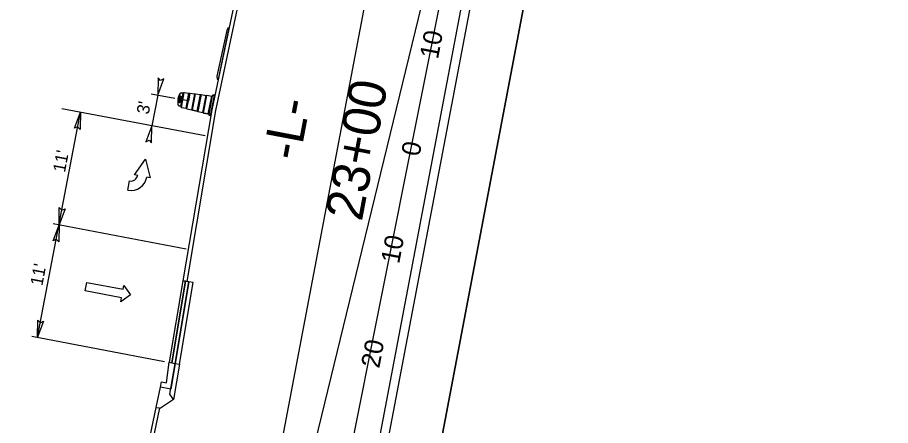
# Model space of a CAD drawing. Extents: x 1615680 to 1617075, y 898420 to 901168.
# Drawn here: x 1616656.3 to 1617075.3, y 899834.6 to 900030.6 of the extents above; entities that cross this region are included whole.
import ezdxf

# ---------------------------------------------------------------- set-up
doc = ezdxf.new("R2010")
doc.units = 0
for name, color, linetype in [('Default', 7, 'Continuous'), ('DEV BORDER CELL', 7, 'Continuous'), ('DEV DRUM SECTIONAL VIEW CELL', 7, 'Continuous'), ('Gray Area Fill Shapes', 7, 'Continuous'), ('North Arrow', 7, 'Continuous'), ('Old_Level_11', 7, 'Continuous'), ('Prop CMT Pvmt Course 1', 7, 'Continuous'), ('Prop CMT Pvmt Course 2', 7, 'Continuous'), ('Prop CMT Pvmt Course 3', 7, 'Continuous'), ('Prop CMT Subgrade Earthwork', 7, 'Continuous'), ('Prop Conc 4in Sidewalk', 7, 'Continuous'), ('Prop Conc Curb and Gutter', 7, 'Continuous'), ('Prop Conc Island Cover', 7, 'Continuous'), ('Prop Dimension Text', 7, 'Continuous'), ('Prop XS Finish Grade', 7, 'Continuous'), ('Prop XS Offset Labels', 7, 'Continuous'), ('Prop XS Station Labels', 7, 'Continuous'), ('Scratch_Level_0', 7, 'Continuous'), ('Scratch_Level_9', 7, 'Continuous'), ('Sheet Clip Boundary CELL', 7, 'Continuous'), ('Sheet Cross Section CELL', 7, 'Continuous'), ('Sheet Plot Border Outside CELL', 7, 'Continuous')]:
    doc.layers.add(name, color=color, linetype=linetype)

msp = doc.modelspace()

# ---------------------------------------------------------------- linework, layer by layer
at = {"layer": 'Default'}
for points in [[(1616723.79, 900001.53), (1616723.65, 899993.31), (1616726.58, 900001.05), (1616724.97, 900000.3)], [(1616683.66, 899977.39), (1616686.54, 899985.09), (1616686.44, 899976.82), (1616685.22, 899978.1)], [(1616720.71, 899970.36), (1616720.85, 899978.58), (1616717.91, 899970.84), (1616719.52, 899971.59)], [(1616679.16, 899938.75), (1616676.28, 899931.05), (1616676.39, 899939.33), (1616677.61, 899938.04)], [(1616673.4, 899923.36), (1616676.28, 899931.05), (1616676.18, 899922.78), (1616674.96, 899924.07)], [(1616668.91, 899884.72), (1616666.02, 899877.02), (1616666.13, 899885.29), (1616667.35, 899884.01)]]:
    msp.add_lwpolyline(points, close=True, dxfattribs=at)
at = {"layer": 'DEV BORDER CELL'}
msp.add_lwpolyline([(1616014.55, 901139.21), (1615734.74, 899665.53), (1616766.32, 899469.67), (1617046.12, 900943.35)], close=True, dxfattribs=at)
at = {"layer": 'DEV DRUM SECTIONAL VIEW CELL'}
for p, q in [((1616734.63, 899992.82), (1616734.6, 899992.83)), ((1616734.7, 899988.02), (1616735.87, 899994.18)), ((1616734.99, 899987.43), (1616736.36, 899994.63)), ((1616735.87, 899994.18), (1616735.15, 899994.32)), ((1616736.36, 899994.63), (1616738.66, 899994.19)), ((1616737.3, 899986.99), (1616738.66, 899994.19)), ((1616737.65, 899986.74), (1616739.08, 899994.29)), ((1616738.66, 899994.19), (1616739.08, 899994.29)), ((1616739.08, 899994.29), (1616741.39, 899993.85)), ((1616739.96, 899986.3), (1616741.39, 899993.85)), ((1616740.31, 899986.06), (1616741.81, 899993.96)), ((1616741.39, 899993.85), (1616741.81, 899993.96)), ((1616741.81, 899993.96), (1616744.12, 899993.52)), ((1616742.62, 899985.62), (1616744.12, 899993.52)), ((1616742.97, 899985.37), (1616744.54, 899993.62)), ((1616744.12, 899993.52), (1616744.54, 899993.62)), ((1616744.54, 899993.62), (1616746.85, 899993.18)), ((1616745.28, 899984.93), (1616746.85, 899993.18)), ((1616745.63, 899984.69), (1616747.26, 899993.28)), ((1616746.85, 899993.18), (1616747.26, 899993.28)), ((1616747.26, 899993.28), (1616749.57, 899992.84)), ((1616747.94, 899984.25), (1616749.57, 899992.84)), ((1616748.28, 899983.95), (1616750, 899992.99)), ((1616748.98, 899983.42), (1616750.84, 899993.23)), ((1616749.57, 899992.84), (1616749.99, 899992.94)), ((1616750.84, 899993.23), (1616750.46, 899993.31)), ((1616734.7, 899988.02), (1616733.98, 899988.16)), ((1616734.05, 899989.74), (1616734.01, 899989.75)), ((1616734.99, 899987.43), (1616737.3, 899986.99)), ((1616737.3, 899986.99), (1616737.65, 899986.74)), ((1616737.65, 899986.74), (1616739.96, 899986.3)), ((1616739.96, 899986.3), (1616740.31, 899986.06)), ((1616740.31, 899986.06), (1616742.62, 899985.62)), ((1616742.62, 899985.62), (1616742.97, 899985.37)), ((1616742.97, 899985.37), (1616745.28, 899984.93)), ((1616745.28, 899984.93), (1616745.63, 899984.69)), ((1616745.63, 899984.69), (1616747.94, 899984.25)), ((1616747.94, 899984.25), (1616748.29, 899984)), ((1616748.98, 899983.42), (1616748.59, 899983.49))]:
    msp.add_line(p, q, dxfattribs=at)
for points in [[(1616737.65, 899986.74), (1616738.37, 899990.52), (1616734.52, 899991.25), (1616734.48, 899991.06), (1616734.46, 899990.92), (1616734.44, 899990.77), (1616734.42, 899990.62), (1616734.4, 899990.44), (1616734.39, 899990.27), (1616734.38, 899990.08), (1616734.37, 899989.95), (1616734.34, 899989.89), (1616734.31, 899989.83), (1616734.25, 899989.78), (1616734.2, 899989.76), (1616734.14, 899989.74), (1616734.09, 899989.74), (1616733.98, 899989.76), (1616733.93, 899989.78), (1616733.87, 899989.83), (1616733.82, 899989.89), (1616733.79, 899989.97), (1616733.79, 899990.03), (1616733.8, 899990.17), (1616733.81, 899990.36), (1616733.85, 899990.76), (1616733.89, 899991.04), (1616733.92, 899991.25), (1616733.94, 899991.36), (1616733.46, 899991.45), (1616733.42, 899991.25), (1616733.38, 899990.99), (1616733.34, 899990.72), (1616733.32, 899990.44), (1616733.31, 899990.16), (1616733.3, 899989.86), (1616733.3, 899989.52), (1616733.31, 899989.32), (1616733.34, 899988.99), (1616733.35, 899988.85), (1616733.36, 899988.75), (1616733.4, 899988.65), (1616733.44, 899988.55), (1616733.52, 899988.44), (1616733.6, 899988.36), (1616733.67, 899988.29), (1616733.76, 899988.24), (1616733.86, 899988.19), (1616733.98, 899988.16), (1616734.7, 899988.02), (1616734.72, 899987.95), (1616734.74, 899987.87), (1616734.78, 899987.76), (1616734.83, 899987.66), (1616734.89, 899987.57), (1616734.99, 899987.43), (1616737.3, 899986.99)], [(1616739.08, 899994.29), (1616738.37, 899990.52), (1616734.52, 899991.25), (1616734.58, 899991.57), (1616734.64, 899991.79), (1616734.69, 899991.98), (1616734.74, 899992.14), (1616734.79, 899992.32), (1616734.84, 899992.46), (1616734.86, 899992.53), (1616734.85, 899992.6), (1616734.83, 899992.68), (1616734.78, 899992.74), (1616734.73, 899992.79), (1616734.67, 899992.82), (1616734.6, 899992.83), (1616734.51, 899992.83), (1616734.42, 899992.8), (1616734.37, 899992.77), (1616734.34, 899992.73), (1616734.31, 899992.7), (1616734.29, 899992.65), (1616734.25, 899992.52), (1616734.2, 899992.4), (1616734.17, 899992.27), (1616734.12, 899992.14), (1616734.08, 899991.97), (1616734.03, 899991.78), (1616734, 899991.64), (1616733.97, 899991.51), (1616733.94, 899991.36), (1616733.46, 899991.45), (1616733.5, 899991.68), (1616733.54, 899991.85), (1616733.6, 899992.09), (1616733.65, 899992.26), (1616733.7, 899992.44), (1616733.77, 899992.65), (1616733.86, 899992.89), (1616733.95, 899993.12), (1616734.06, 899993.4), (1616734.17, 899993.63), (1616734.26, 899993.82), (1616734.31, 899993.91), (1616734.36, 899993.99), (1616734.42, 899994.07), (1616734.5, 899994.15), (1616734.58, 899994.2), (1616734.67, 899994.26), (1616734.76, 899994.29), (1616734.86, 899994.32), (1616734.94, 899994.33), (1616735.04, 899994.33), (1616735.12, 899994.32), (1616735.15, 899994.32), (1616735.87, 899994.18), (1616735.96, 899994.31), (1616736.02, 899994.37), (1616736.09, 899994.44), (1616736.16, 899994.5), (1616736.26, 899994.58), (1616736.32, 899994.61), (1616736.36, 899994.63), (1616738.66, 899994.19)], [(1616739.96, 899986.3), (1616741.39, 899993.85), (1616741.81, 899993.96), (1616744.12, 899993.52), (1616744.54, 899993.62), (1616742.97, 899985.37), (1616742.62, 899985.62), (1616740.31, 899986.06)], [(1616745.28, 899984.93), (1616746.85, 899993.18), (1616747.26, 899993.28), (1616749.57, 899992.84), (1616749.99, 899992.94), (1616750.01, 899993.04), (1616750.03, 899993.1), (1616750.08, 899993.16), (1616750.13, 899993.22), (1616750.18, 899993.25), (1616750.24, 899993.29), (1616750.32, 899993.31), (1616750.37, 899993.31), (1616750.42, 899993.31), (1616750.46, 899993.31), (1616750.84, 899993.23), (1616748.98, 899983.42), (1616748.59, 899983.49), (1616748.54, 899983.5), (1616748.48, 899983.53), (1616748.43, 899983.56), (1616748.39, 899983.6), (1616748.36, 899983.64), (1616748.31, 899983.7), (1616748.29, 899983.77), (1616748.28, 899983.84), (1616748.27, 899983.89), (1616748.28, 899983.95), (1616748.29, 899984), (1616747.94, 899984.25), (1616745.63, 899984.69)]]:
    msp.add_lwpolyline(points, close=True, dxfattribs=at)
for centre, radius, start, end in [((1616742.14, 899989.8), 8.85, 152.3001, 186.1986), ((1616742.63, 899989.71), 8.85, 160.5754, 177.9234), ((1616734.55, 899992.56), 0.274, 79.2494, 160.5754), ((1616735.01, 899993.55), 0.783, 79.2494, 152.3001), ((1616743.21, 899989.6), 8.85, 161.1006, 177.3981), ((1616734.58, 899992.55), 0.274, 341.1006, 79.2494), ((1616737.01, 899993.44), 1.35, 118.7358, 146.9434), ((1616750.39, 899992.92), 0.392, 79.2494, 169.2494), ((1616734.13, 899988.93), 0.783, 186.1986, 259.2494), ((1616734.06, 899990.02), 0.274, 177.9234, 259.2494), ((1616734.1, 899990.01), 0.274, 259.2494, 357.3981), ((1616736.03, 899988.29), 1.35, 191.5554, 219.7629), ((1616748.67, 899983.88), 0.392, 169.2494, 259.2494)]:
    msp.add_arc(centre, radius, start, end, dxfattribs=at)
at = {"layer": 'Gray Area Fill Shapes'}
msp.add_line((1616752.74, 900000.91), (1616757.9, 900025.38), dxfattribs=at)
msp.add_lwpolyline([(1616757.9, 900025.38), (1616757.28, 900025.49), (1616756.74, 900024.32), (1616752.05, 900002.33), (1616752.13, 900001.03), (1616752.74, 900000.91)], dxfattribs=at)
at = {"layer": 'North Arrow'}
msp.add_line((1616746.37, 899973.73), (1616677.66, 899986.78), dxfattribs=at)
at = {"layer": 'Old_Level_11'}
for p, q in [((1616720.48, 899993.91), (1616731.79, 899991.77)), ((1616723.65, 899993.31), (1616720.85, 899978.58)), ((1616666.02, 899877.02), (1616686.54, 899985.09)), ((1616673.46, 899931.59), (1616737.23, 899919.48)), ((1616663.2, 899877.56), (1616726.97, 899865.45))]:
    msp.add_line(p, q, dxfattribs=at)
at = {"layer": 'Prop CMT Pvmt Course 1'}
for p, q in [((1616765.99, 900063.81), (1616749.65, 899986.23)), ((1616749.65, 899986.23), (1616735.77, 899904.19)), ((1616749.65, 899986.23), (1616749.65, 899986.23)), ((1616750.78, 899986.02), (1616750.78, 899986.02)), ((1616735.77, 899904.19), (1616736.89, 899903.98)), ((1616735.77, 899904.19), (1616735.77, 899904.19)), ((1616735.77, 899904.19), (1616735.77, 899904.19)), ((1616736.89, 899903.98), (1616736.89, 899903.98))]:
    msp.add_line(p, q, dxfattribs=at)
msp.add_lwpolyline([(1616735.77, 899904.19), (1616729.14, 899865.04), (1616729.14, 899865.04), (1616730.37, 899864.8), (1616737, 899903.96), (1616737, 899903.96), (1616735.77, 899904.19), (1616735.77, 899904.19), (1616735.77, 899904.19)], dxfattribs=at)
at = {"layer": 'Prop CMT Pvmt Course 2'}
msp.add_lwpolyline([(1616737, 899903.96), (1616730.37, 899864.8), (1616730.37, 899864.8), (1616732.01, 899864.49), (1616738.63, 899903.65), (1616738.63, 899903.65), (1616737, 899903.96), (1616737, 899903.96), (1616737, 899903.96)], dxfattribs=at)
at = {"layer": 'Prop CMT Pvmt Course 3'}
for p, q in [((1616751.59, 899985.86), (1616768.11, 900064.28)), ((1616737.71, 899903.82), (1616751.59, 899985.86)), ((1616750.78, 899986.02), (1616750.78, 899986.02)), ((1616751.59, 899985.86), (1616751.59, 899985.86)), ((1616736.89, 899903.98), (1616737.71, 899903.82)), ((1616736.89, 899903.98), (1616736.89, 899903.98)), ((1616736.89, 899903.98), (1616736.89, 899903.98)), ((1616737.71, 899903.82), (1616737.71, 899903.82))]:
    msp.add_line(p, q, dxfattribs=at)
for points in [[(1616738.63, 899903.65), (1616732.01, 899864.49), (1616732.01, 899864.49), (1616734.05, 899864.1), (1616740.68, 899903.26), (1616740.68, 899903.26), (1616738.63, 899903.65), (1616738.63, 899903.65), (1616738.63, 899903.65)], [(1616732.01, 899864.49), (1616734.05, 899864.1), (1616731.19, 899847.21), (1616729.5, 899849.69), (1616732.01, 899864.49)]]:
    msp.add_lwpolyline(points, dxfattribs=at)
at = {"layer": 'Prop CMT Subgrade Earthwork'}
for points in [[(1616734.05, 899864.1), (1616740.68, 899903.26), (1616740.68, 899903.26)], [(1616734.05, 899864.1), (1616731.19, 899847.21)], [(1616731.19, 899847.21), (1616724.43, 899842.61)]]:
    msp.add_lwpolyline(points, dxfattribs=at)
at = {"layer": 'Prop Conc 4in Sidewalk'}
msp.add_lwpolyline([(1616722.88, 899843.32), (1616724.53, 899843.06), (1616719.35, 899818.49), (1616717.73, 899818.85), (1616722.88, 899843.32)], dxfattribs=at)
at = {"layer": 'Prop Conc Curb and Gutter'}
msp.add_lwpolyline([(1616729.14, 899865.04), (1616729.14, 899865.04), (1616729.14, 899865.04), (1616732.01, 899864.49), (1616732.01, 899864.49), (1616729.92, 899852.16), (1616724.94, 899853.11), (1616724.94, 899853.11), (1616725.41, 899855.56), (1616725.41, 899855.56), (1616725.41, 899855.56), (1616727.87, 899855.1), (1616729.14, 899865.04)], dxfattribs=at)
at = {"layer": 'Prop Conc Island Cover'}
msp.add_lwpolyline([(1616752.13, 900001.03), (1616752.74, 900000.91), (1616752.74, 900000.91), (1616757.9, 900025.38), (1616757.28, 900025.49), (1616757.28, 900025.49), (1616756.74, 900024.32), (1616756.74, 900024.32), (1616752.05, 900002.33), (1616752.05, 900002.33), (1616752.05, 900002.33), (1616752.13, 900001.03), (1616752.13, 900001.03)], dxfattribs=at)
at = {"layer": 'Prop Dimension Text'}
for p, q in [((1616712.53, 899955.02), (1616717.81, 899962.56)), ((1616717.81, 899962.56), (1616719.96, 899953.61)), ((1616714.04, 899954.73), (1616712.53, 899955.02)), ((1616719.96, 899953.61), (1616718.46, 899953.89)), ((1616709.34, 899947.68), (1616710.18, 899952.1)), ((1616688.86, 899899.26), (1616689.63, 899903.36)), ((1616689.63, 899903.36), (1616707.04, 899900.06)), ((1616706.26, 899895.96), (1616688.86, 899899.26)), ((1616707.04, 899900.06), (1616707.4, 899901.92)), ((1616707.4, 899901.92), (1616710.58, 899897.33)), ((1616710.58, 899897.33), (1616705.91, 899894.09)), ((1616705.91, 899894.09), (1616706.26, 899895.96))]:
    msp.add_line(p, q, dxfattribs=at)
for radius in [7.8, 3.3]:
    msp.add_arc((1616710.79, 899955.35), radius, 259.2494, 349.2494, dxfattribs=at)
at = {"layer": 'Prop XS Finish Grade'}
msp.add_lwpolyline([(1616722.88, 899843.32), (1616724.94, 899853.11), (1616724.94, 899853.11)], dxfattribs=at)
at = {"layer": 'Scratch_Level_0'}
msp.add_lwpolyline([(1616054.34, 901080.76), (1615793.19, 899705.33), (1616726.52, 899528.12), (1616890.46, 900391.55), (1616774.26, 900413.61), (1616871.48, 900925.61)], close=True, dxfattribs=at)
at = {"layer": 'Scratch_Level_9'}
msp.add_lwpolyline([(1616729.14, 899865.04), (1616730.37, 899864.8)], dxfattribs=at)
at = {"layer": 'Sheet Clip Boundary CELL'}
for points in [[(1616176.29, 901060.7), (1616848.46, 900914.27), (1616896.28, 900812.91), (1616872.94, 900688.21), (1616835.87, 900695.21), (1616753.94, 900262.18), (1616898.09, 900233.43), (1616734.79, 899562.1), (1616202.98, 899609.43), (1616198.71, 899647.14), (1615822.69, 899825.07), (1616054.34, 901080.76)], [(1616176.29, 901060.7), (1616914, 900899.99), (1616896.28, 900812.91), (1616872.94, 900688.21), (1616835.87, 900695.21), (1616753.94, 900262.18), (1616898.09, 900233.43), (1616747.89, 899480.25), (1615915.8, 899646.19), (1615751.76, 899738.03), (1615981.58, 900932.46), (1616145.94, 900899.57)]]:
    msp.add_lwpolyline(points, close=True, dxfattribs=at)
at = {"layer": 'Sheet Cross Section CELL'}
msp.add_line((1616774.52, 899535.75), (1616938.37, 900398.7), dxfattribs=at)
at = {"layer": 'Sheet Plot Border Outside CELL'}
for points in [[(1616760.47, 899304.87), (1615679.78, 899510.06), (1615994.65, 901168.43), (1617075.34, 900963.24)], [(1616760.47, 899304.87), (1617075.34, 900963.24), (1615994.65, 901168.43), (1615679.78, 899510.06)]]:
    msp.add_lwpolyline(points, close=True, dxfattribs=at)

# ---------------------------------------------------------------- texts
at = {"layer": 'Default'}
for s, rotation, p in [("3'", 79.2494, (1616719.3, 899983.75)), ("11'", 79.2493, (1616679.13, 899955.9)), ("11'", 79.2493, (1616668.27, 899901.43))]:
    msp.add_text(s, height=6, rotation=rotation, dxfattribs=at).set_placement(p)
at = {"layer": 'Prop XS Offset Labels'}
for s, p in [('10', (1616858.13, 900010.23)), ('0', (1616849.27, 899963.55)), ('10', (1616839.48, 899911.98)), ('20', (1616829.95, 899861.8))]:
    msp.add_text(s, height=9, rotation=79.2494, dxfattribs=at).set_placement(p)
at = {"layer": 'Prop XS Station Labels'}
for s, p in [('23+00', (1616821.57, 899932.26)), ('-L-', (1616791.59, 899961.3))]:
    msp.add_text(s, height=18, rotation=79.2494, dxfattribs=at).set_placement(p)
at = {"layer": 'Scratch_Level_9'}
for p in [(1616729.14, 899865.04), (1616729.14, 899865.04), (1616727.87, 899855.1), (1616722.88, 899843.32)]:
    msp.add_text('X', height=0.00125, rotation=79.2494, dxfattribs=at).set_placement(p)

doc.saveas('drawing.dxf')
